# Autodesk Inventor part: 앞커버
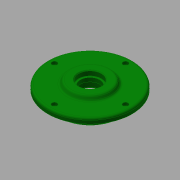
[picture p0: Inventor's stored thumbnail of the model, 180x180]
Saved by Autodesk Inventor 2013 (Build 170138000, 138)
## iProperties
Created: 2016-11
Part Number: 앞커버
Material: 일반
Document SubType Name: Modeling
Designer: mduedu
Density: 1 g/cm^3
Author: mduedu
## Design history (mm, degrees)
sketch "스케치1"
  geometry: L1 (28.5, -17.5)-(28.5, -30); L2 (28.5, -30)-(22.5, -33.464); L3 (22.5, -33.464)-(22.5, -65); L4 (22.5, -65)-(14.5, -65); L5 (14.5, -65)-(14.5, -47.5); L6 (14.5, -47.5)-(0, -47.5); L7 (0, -47.5)-(0, -23.5); L8 (0, 0)-(28.5, 0); L9 (14.5, -23.5)-(14.5, -15); L10 (14.5, -15)-(20.5, -15); L11 (20.5, -15)-(20.5, -17.5); L12 (0, -23.5)-(14.5, -23.5); L13 (20.5, -17.5)-(28.5, -17.5)
  constraints: 26 end point, 8 parallel, 3 perpendicular, 2 horizontal, 2 vertical alignment, 1 collinear
  dimensions: "d0" = 14.5 distance of L5.end L6.end; "d2" = 8 distance of L3.end L4.end; "d3" = 6 distance between parallel lines of L1 L3; "d4" = 120 deg angle of L3 L2; "d5" = 8 distance of L11.end L1.start; "d6" = 60 diameter of L1.end L8; "d7" = 30 diameter of L10 L8; "d8" = 47 diameter of L12 L8; "d9" = 35 diameter of L13 L8; "d10" = 95 diameter of L6 L8; "d11" = 130 diameter of L4 L8
revolve "회전1" sketch "스케치1" stored, may be unused: angle "d12" = 90 deg
fillet "모깎기1" dims "d13" = 0.5
fillet "모깎기2" dims "d14" = 3
chamfer "모따기1" distance "d15" = 1; stored, may be unused: second distance "d16" = 2, angle "d17" = 45 deg
fillet "모깎기3" dims "d18" = 0.3
sketch "스케치2" dims "d19" = 110
  geometry: 6 further points
  constraints: 2 vertical alignment, 1 coincident, 7 other
  dimensions: "d22" = 360 deg dimension on point (0, 0) point (0, 55) (derived)
sketch "스케치3"
  geometry: 4 further points
  constraints: 4 other
hole "구멍1" sketch "스케치3" at (0, 55), (-55, 0), (55, 0), (0, -55) diameter "d24" = 4.5; stored, may be unused: countersink angle "d28" = 90 deg, drill point angle "d30" = 0 deg; dims "d25" = 6, "d26" = 8, "d27" = 4.6, "d29" = 8
node "솔리드1"
